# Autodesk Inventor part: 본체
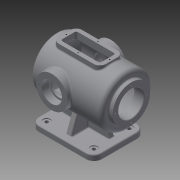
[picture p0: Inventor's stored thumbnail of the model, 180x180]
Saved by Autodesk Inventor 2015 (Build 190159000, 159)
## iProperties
Created: 2021-11
Part Number: 본체
Material: 일반
Document SubType Name: Modeling
Designer: 101548
Density: 1 g/cm^3
Appearance: 기본값
Author: 101548
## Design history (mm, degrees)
sketch "스케치1"
  geometry: L1 (80, -65)-(-80, -65); L2 (-80, -65)-(-80, 65); L3 (-80, 65)-(80, 65); L4 (80, 65)-(80, -65); L5 (80, -65)-(-80, 65); L6 (-80, -65)-(80, 65); 1 further point
  constraints: 12 end point, 2 midpoint, 2 parallel, 1 horizontal, 1 perpendicular
  dimensions: "d0" = 160 distance of L2.end L3.end; "d1" = 130 distance of L1.end L2.end
extrude "돌출1" new body sketch "스케치1" distance "d2" = 14; taper "d3" = 0 deg
sketch "스케치2"
  geometry: L1 (60, -7)-(-60, -7); L2 (-60, -7)-(-60, 7); L3 (-60, 7)-(60, 7); L4 (60, 7)-(60, -7); L5 (60, -7)-(-60, 7); L6 (-60, -7)-(60, 7); L7 (7, -50)-(-7, -50); L8 (-7, -50)-(-7, 50); L9 (-7, 50)-(7, 50); L10 (7, 50)-(7, -50); L11 (7, -50)-(-7, 50); L12 (-7, -50)-(7, 50); 1 further point
  constraints: 24 end point, 4 midpoint, 4 parallel, 2 horizontal, 2 perpendicular
  dimensions: "d4" = 14 distance of L1.end L2.end; "d5" = 14 distance of L8.end L9.end; "d6" = 120 distance of L2.end L3.end; "d7" = 100 vertical distance of L7.start L8.end
extrude "돌출2" join sketch "스케치2" distance "d8" = 100; taper "d9" = 0 deg
node "작업 평면1"
sketch "스케치3"
  geometry: L1 (-7, 114)-(7, 114) reference; C1 r 65 at (0, 114); 1 further point
  constraints: 1 centre point, 1 midpoint
  dimensions: "d11" = 130 diameter of C1
extrude "돌출3" join sketch "스케치3" distance "d12" = 200; taper "d13" = 0 deg
sketch "스케치4"
  geometry: C1 r 65 at (0, 0) reference; C2 r 47.5 at (0, 0); 1 further point
  constraints: 1 centre point, 1 coincident
  dimensions: "d14" = 95 diameter of C2
extrude "돌출4" join sketch "스케치4" distance "d15" = 10; taper "d16" = 0 deg
sketch "스케치5"
  geometry: L1 (-80, 0)-(-80, 14) reference; L2 (-80, 14)-(-60, 14) reference; L3 (-60, 14)-(-60, 49) reference; L4 (-60, 49)-(-100, 49) reference; L5 (-100, 49)-(-100, 66.5) reference; L6 (-100, 66.5)-(-110, 66.5) reference; L7 (-110, 66.5)-(-110, 161.5) reference; L8 (-110, 161.5)-(-100, 161.5) reference; L9 (-100, 161.5)-(-100, 179) reference; L10 (-100, 179)-(100, 179) reference; L11 (100, 179)-(100, 49) reference; L12 (100, 49)-(60, 49) reference; L13 (60, 49)-(60, 14) reference; L14 (60, 14)-(80, 14) reference; L15 (80, 14)-(80, 0) reference; L16 (80, 0)-(-80, 0) reference; L17 (80, 114)-(0, 114); L18 (100, 114)-(100, 179); A1 r 100 centre (0, 114) between (100, 114) and (75.993, 179); 1 further point
  constraints: 4 end point, 2 point on circle, 2 point on line, 1 centre point, 1 horizontal, 1 tangent, 1 vertical
  dimensions: "d19" = 100 radius of A1; "d20" = 24.00658 distance from line of A1.end L11
revolve "회전1" sketch "스케치5" stored, may be unused: angle "d18" = 90 deg
sketch "스케치6"
  geometry: C1 r 47.5 at (0, 0) reference; C2 r 32.5 at (0, 0); 1 further point
  constraints: 1 centre point, 1 coincident
  dimensions: "d21" = 65 diameter of C2
extrude "돌출5" cut sketch "스케치6" distance "d22" = 25; taper "d23" = 0 deg
sketch "스케치7"
  geometry: L1 (-80, 0)-(-80, 14) reference; L2 (-80, 14)-(-60, 14) reference; L3 (-60, 14)-(-60, 49) reference; L4 (-60, 49)-(-100, 49) reference; L5 (-100, 49)-(-100, 66.5) reference; L6 (-100, 66.5)-(-110, 66.5) reference; L7 (-110, 66.5)-(-110, 81.5) reference; L8 (-110, 81.5)-(-85, 81.5) reference; L9 (-85, 81.5)-(-85, 146.5) reference; L10 (-85, 146.5)-(-110, 146.5) reference; L11 (-110, 146.5)-(-110, 161.5) reference; L12 (-110, 161.5)-(-100, 161.5) reference; L13 (-100, 161.5)-(-100, 179) reference; L14 (-100, 179)-(75.993, 179) reference; L15 (60, 49)-(60, 14) reference; L16 (60, 14)-(80, 14) reference; L17 (80, 14)-(80, 0) reference; L18 (80, 0)-(-80, 0) reference; L19 (71.239, 169)-(-85, 169); L20 (-85, 81.5)-(-85, 146.5) reference; L21 (-85, 114)-(90, 114); L22 (75.993, 49)-(60, 49) reference; L23 (-85, 114)-(-85, 169); A1 r 100 centre (0, 114) between (75.993, 49) and (75.993, 179) reference; A2 r 90 centre (0, 114) between (90, 114) and (71.239, 169); 2 further points
  constraints: 7 end point, 2 point on circle, 1 centre point, 1 midpoint, 1 point on line
  dimensions: "d24" = 10 radial gap between concentric circles of A1 A2; "d29" = 90 deg angle of L20 L21; "d112" = 156.23903 distance from line of L19.start L23; "d114" = 156.23903 distance of L19.start L19.end; "d115" = 175 distance of L21.start L21.end
revolve "회전2" sketch "스케치7" stored, may be unused: angle "d30" = 90 deg
fillet "모깎기1" dims "d31" = 3
fillet "모깎기2" dims "d32" = 3
chamfer "모따기1" distance "d33" = 1; stored, may be unused: second distance "d34" = 2, angle "d35" = 45 deg
sketch "스케치8"
  geometry: 1 further point
feature "면 기울기1" dims angle "d36" = 20 deg
sketch "스케치9" dims "d38" = 80
  geometry: C1 r 47.5 at (0, 0) reference; C2 r 33.5 at (0, 0) reference; 3 further points
  constraints: 2 horizontal alignment, 1 coincident, 2 other
hole "구멍1" sketch "스케치9" at (-40, 0) diameter "d39" = 3.242; stored, may be unused: countersink angle "d43" = 90 deg, drill point angle "d45" = 118 deg; dims "d40" = 11, "d41" = 4, "d42" = 2, "d44" = 13
node "작업 평면2"
sketch "스케치10"
  geometry: L1 (60, -30)-(-60, -30); L2 (-60, -30)-(-60, 30); L3 (-60, 30)-(60, 30); L4 (60, 30)-(60, -30); L5 (60, -30)-(-60, 30); L6 (-60, -30)-(60, 30); 1 further point
  constraints: 12 end point, 2 midpoint, 2 parallel, 1 horizontal, 1 perpendicular
  dimensions: "d50" = 120 distance of L2.end L3.end; "d51" = 60 distance of L1.end L2.end
extrude "돌출6" join sketch "스케치10" stored distance "d52" = 25; taper "d53" = 0 deg
sketch "스케치11"
  geometry: L1 (60, -30)-(-60, -30) reference; L2 (60, 30)-(60, -30) reference; L3 (-60, 30)-(60, 30) reference; L4 (-60, -30)-(-60, 30) reference; L5 (50, 20)-(50, -20); L6 (50, -20)-(-50, -20); L7 (-50, -20)-(-50, 20); L8 (-50, 20)-(50, 20); 1 further point
  constraints: 8 end point, 3 other
  dimensions: "d54" = 10 distance between parallel lines of L3 L8
extrude "돌출7" cut sketch "스케치11" stored distance "d55" = 25; taper "d56" = 0 deg
fillet "모깎기3" dims "d57" = 5
fillet "모깎기4" dims "d58" = 15
sketch "스케치12"
  geometry: L1 (60, 15)-(60, -15) reference; L2 (-45, 30)-(45, 30) reference; L3 (-60, -15)-(-60, 15) reference; L4 (45, -30)-(-45, -30) reference; L5 (55, 15)-(55, -15); L6 (45, -25)-(-45, -25); L7 (-55, -15)-(-55, 15); L8 (-45, 25)-(45, 25); A1 r 15 centre (45, -15) between (45, -30) and (60, -15) reference; A2 r 15 centre (45, 15) between (60, 15) and (45, 30) reference; A3 r 15 centre (-45, 15) between (-45, 30) and (-60, 15) reference; A4 r 15 centre (-45, -15) between (-60, -15) and (-45, -30) reference; A5 r 10 centre (45, 15) between (55, 15) and (45, 25); A6 r 10 centre (45, -15) between (45, -25) and (55, -15); A7 r 10 centre (-45, -15) between (-55, -15) and (-45, -25); A8 r 10 centre (-45, 15) between (-45, 25) and (-55, 15); 5 further points
  constraints: 8 end point, 8 point on circle, 4 centre point, 4 midpoint, 1 horizontal alignment, 7 other
  dimensions: "d59" = 5 distance between parallel lines of L2 L8
hole "구멍2" sketch "스케치12" at (0, 25), (0, -25), (-55, 0), (55, 0) diameter "d60" = 3.242; stored, may be unused: countersink angle "d64" = 90 deg, drill point angle "d66" = 118 deg; dims "d61" = 9, "d62" = 4, "d63" = 2, "d65" = 11
node "작업 평면3"
sketch "스케치13"
  geometry: L1 (-45, 184)-(45, 184) reference; L2 (-100, 49)-(-100, 179) reference; L3 (75.993, 179)-(75.993, 49) reference; L4 (-60, 177.246)-(-60, 177.246) reference; L5 (-45, 171.663)-(45, 171.663) reference; L6 (60, 177.246)-(60, 177.246) reference; L7 (45, 171.663)-(-45, 171.663) reference; L8 (-7, 49.378)-(-7, 72.467) reference; L9 (-47.123, 49.378)-(-7, 49.378) reference; L10 (-47.123, 49.378)-(-47.123, 49.378) reference; L11 (-7, 49.378)-(-47.123, 49.378) reference; L12 (-7, 72.467)-(-7, 49.378) reference; L13 (7, 72.467)-(-7, 72.467) reference; L14 (7, 49.378)-(7, 72.467) reference; L15 (47.123, 49.378)-(7, 49.378) reference; L16 (47.123, 49.378)-(47.123, 49.378) reference; L17 (7, 49.378)-(47.123, 49.378) reference; L18 (7, 72.467)-(7, 49.378) reference; L19 (-7, 72.467)-(7, 72.467) reference; C1 r 40 at (17, 114); 2 further points
  constraints: 1 centre point, 1 horizontal alignment, 1 midpoint, 4 other
  dimensions: "d68" = 80 diameter of C1; "d70" = 17 horizontal distance of C1.centre point (0, 0)
extrude "돌출8" join sketch "스케치13" stored distance "d71" = 25; taper "d72" = 0 deg
fillet "모깎기5" dims "d73" = 3
sketch "스케치14"
  geometry: C1 r 40 at (0, 0) reference; C2 r 26 at (0, 0); 1 further point
  constraints: 1 centre point, 1 coincident
  dimensions: "d74" = 52 diameter of C2
extrude "돌출9" cut sketch "스케치14" distance "d75" = 18; taper "d76" = 0 deg
sketch "스케치15"
  geometry: C1 r 26 at (0, 0) reference; C2 r 21 at (0, 0); 1 further point
  constraints: 1 centre point, 1 coincident
  dimensions: "d77" = 42 diameter of C2
extrude "돌출10" cut sketch "스케치15" stored distance "d78" = 18; taper "d79" = 0 deg
sketch "스케치16" dims "d80" = 65
  geometry: C1 r 26 at (0, 0) reference; C2 r 40 at (0, 0) reference; 3 further points
  constraints: 2 vertical alignment, 1 coincident, 2 other
hole "구멍3" sketch "스케치16" at (0, 32.5) diameter "d81" = 3.242; stored, may be unused: countersink angle "d85" = 90 deg, drill point angle "d87" = 118 deg; dims "d82" = 11, "d83" = 4, "d84" = 2, "d86" = 13
fillet "모깎기6" dims "d91" = 3
fillet "모깎기7" dims "d92" = 10
feature "면 기울기3" dims angle "d93" = 20 deg
fillet "모깎기8" dims "d94" = 3
fillet "모깎기9" dims "d95" = 3
fillet "모깎기10" dims "d96" = 3
fillet "모깎기11" dims "d97" = 3
fillet "모깎기12" dims "d98" = 20
fillet "모깎기13" dims "d99" = 3
sketch "스케치17"
  geometry: A1 r 17 centre (60, -45) between (60, -62) and (77, -45) reference; A2 r 17 centre (60, 45) between (77, 45) and (60, 62) reference; A3 r 17 centre (-60, 45) between (-60, 62) and (-77, 45) reference; A4 r 17 centre (-60, -45) between (-77, -45) and (-60, -62) reference; 1 further point
hole "구멍4" sketch "스케치17" at (-60, -45), (-60, 45), (60, 45), (60, -45) diameter "d100" = 9; stored, may be unused: countersink angle "d104" = 90 deg, drill point angle "d106" = 118 deg; dims "d101" = 11, "d102" = 18, "d103" = 2, "d105" = 13
fillet "모깎기14" dims "d107" = 3
sketch "스케치18"
  geometry: L1 (0, 0)-(120, 0) reference; 3 further points
  constraints: 1 midpoint, 1 vertical alignment, 1 other
  dimensions: "d108" = 5 distance of point (60, 0) point (60, -5)
feature "엠보싱1" sketch "스케치18" dims "d5" = 14, "d109" = 0.5, "d110" = 0.5 deg
fillet "모깎기15" dims "d111" = 10
fillet "모깎기16" dims "d116" = 3
fillet "모깎기17" dims "d117" = 0.3
fillet "모깎기18" dims "d118" = 0.3
node "솔리드1"
pattern_circular "원형 패턴1" dims angle "d47" = 360 deg
mirror "대칭1"
pattern_circular "원형 패턴2" dims angle "d89" = 360 deg
mirror "대칭2"
node "투영된 루프1"
node "절단 모서리 투영1"
node "절단 모서리 투영2"
other parameters: "d49" = 184, "d67" = -75
